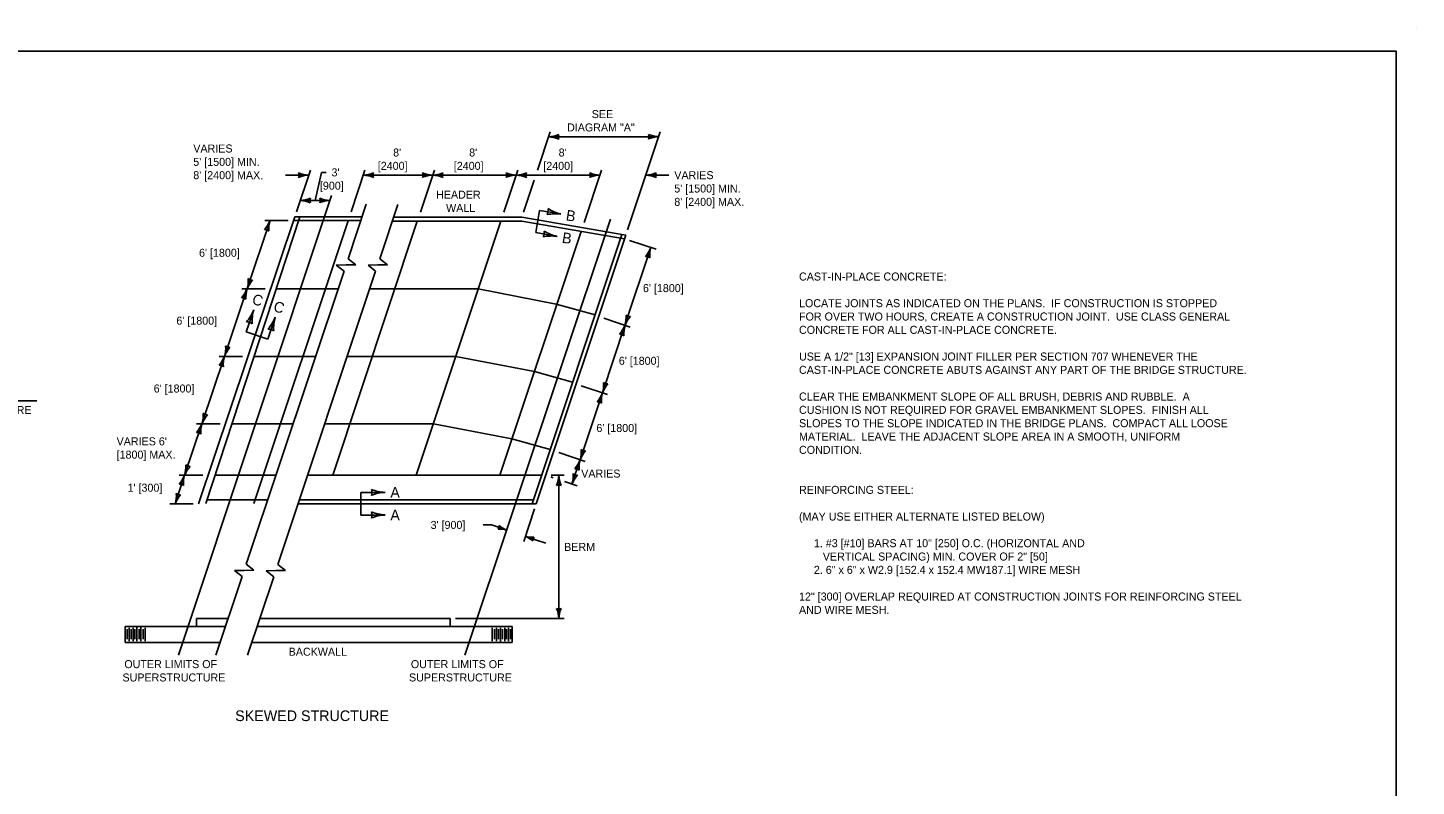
# Model space of a CAD drawing. Extents: x 49991.4 to 50021, y 49987.6 to 50011.4.
# Drawn here: x 50006.49 to 50016.9, y 49993.49 to 49999.18 of the extents above; entities that cross this region are included whole.
import ezdxf

# ---------------------------------------------------------------- set-up
doc = ezdxf.new("R2010")
doc.units = 0
for name, color, linetype in [('Level 1', 7, 'Continuous'), ('Level 2', 7, 'Continuous'), ('Level 3', 7, 'Continuous'), ('Level 4', 7, 'Continuous'), ('Level 5', 7, 'Continuous'), ('Level 6', 7, 'Continuous')]:
    doc.layers.add(name, color=color, linetype=linetype)

msp = doc.modelspace()

# ---------------------------------------------------------------- linework, layer by layer
at = {"layer": 'Level 1'}
for p, q in [((50016.9, 49999.176), (50016.9, 49999.176)), ((50008.492, 49997.757), (50007.772, 49995.606)), ((50007.825, 49995.608), (50008.53, 49997.757)), ((50008.997, 49997.757), (50008.492, 49997.757)), ((50009.234, 49997.754), (50010.194, 49997.754)), ((50010.194, 49997.754), (50010.975, 49997.621)), ((50008.186, 49995.607), (50008.893, 49997.728)), ((50008.482, 49997.729), (50008.987, 49997.729)), ((50008.777, 49995.82), (50009.411, 49997.724)), ((50009.224, 49997.724), (50010.194, 49997.724)), ((50009.403, 49995.82), (50010.038, 49997.724)), ((50010.03, 49995.82), (50010.639, 49997.648)), ((50010.194, 49997.724), (50010.965, 49997.593)), ((50010.272, 49995.606), (50010.945, 49997.626)), ((50010.303, 49995.606), (50010.975, 49997.621)), ((50008.817, 49997.217), (50008.353, 49997.217)), ((50009.055, 49997.217), (50009.867, 49997.217)), ((50009.867, 49997.217), (50010.453, 49997.103)), ((50010.453, 49997.103), (50010.744, 49997.022)), ((50008.648, 49996.711), (50008.187, 49996.711)), ((50008.886, 49996.711), (50009.7, 49996.711)), ((50009.7, 49996.711), (50010.289, 49996.597)), ((50010.289, 49996.597), (50010.575, 49996.517)), ((50008.48, 49996.206), (50008.022, 49996.206)), ((50009.532, 49996.206), (50008.718, 49996.206)), ((50009.532, 49996.206), (50010.121, 49996.092)), ((50010.121, 49996.092), (50010.407, 49996.012)), ((50008.351, 49995.82), (50007.895, 49995.82)), ((50008.589, 49995.82), (50010.343, 49995.82)), ((50008.518, 49995.606), (50010.303, 49995.606)), ((50007.755, 49994.685), (50007.755, 49994.744)), ((50007.755, 49994.744), (50007.993, 49994.744)), ((50008.23, 49994.744), (50009.657, 49994.744)), ((50009.657, 49994.685), (50009.657, 49994.744)), ((50007.22, 49994.566), (50007.22, 49994.685)), ((50007.22, 49994.685), (50007.755, 49994.685)), ((50007.235, 49994.59), (50007.235, 49994.664)), ((50007.25, 49994.574), (50007.25, 49994.676)), ((50007.265, 49994.59), (50007.265, 49994.665)), ((50007.28, 49994.574), (50007.28, 49994.676)), ((50007.294, 49994.591), (50007.294, 49994.665)), ((50007.309, 49994.574), (50007.309, 49994.677)), ((50007.325, 49994.591), (50007.325, 49994.665)), ((50007.339, 49994.575), (50007.339, 49994.677)), ((50007.355, 49994.665), (50007.355, 49994.591)), ((50007.37, 49994.676), (50007.37, 49994.575)), ((50007.755, 49994.685), (50007.933, 49994.685)), ((50007.933, 49994.685), (50007.973, 49994.685)), ((50008.21, 49994.685), (50010.123, 49994.685)), ((50009.973, 49994.676), (50009.973, 49994.574)), ((50009.991, 49994.664), (50009.991, 49994.59)), ((50010.006, 49994.574), (50010.006, 49994.676)), ((50010.021, 49994.59), (50010.021, 49994.664)), ((50010.036, 49994.573), (50010.036, 49994.676)), ((50010.051, 49994.59), (50010.051, 49994.664)), ((50010.067, 49994.574), (50010.067, 49994.676)), ((50010.081, 49994.59), (50010.081, 49994.665)), ((50010.096, 49994.574), (50010.096, 49994.676)), ((50010.111, 49994.591), (50010.111, 49994.665)), ((50010.123, 49994.685), (50010.123, 49994.566)), ((50007.22, 49994.566), (50007.933, 49994.566)), ((50008.171, 49994.566), (50010.123, 49994.566))]:
    msp.add_line(p, q, dxfattribs=at)
msp.add_lwpolyline([(49999.384, 49998.999), (50016.75, 49998.999), (50016.75, 49987.799), (49999.384, 49987.799)], close=True, dxfattribs=at)
at = {"layer": 'Level 3'}
for p, q in [((50010.312, 49998.108), (50010.408, 49998.396)), ((50010.988, 49997.659), (50011.233, 49998.396)), ((50010.395, 49998.358), (50011.221, 49998.358)), ((50008.423, 49998.07), (50008.597, 49998.07)), ((50008.61, 49998.108), (50008.505, 49997.795)), ((50008.692, 49998.091), (50008.645, 49997.88)), ((50008.692, 49998.091), (50008.728, 49998.091)), ((50008.916, 49997.795), (50009.019, 49998.108)), ((50009.007, 49998.07), (50009.518, 49998.07)), ((50009.434, 49997.792), (50009.54, 49998.108)), ((50009.518, 49998.07), (50010.147, 49998.07)), ((50010.061, 49997.792), (50010.166, 49998.108)), ((50010.147, 49998.07), (50010.78, 49998.07)), ((50010.661, 49997.715), (50010.793, 49998.108)), ((50011.125, 49998.07), (50011.298, 49998.07)), ((50010.207, 49997.792), (50010.287, 49998.032)), ((50008.533, 49997.88), (50008.756, 49997.88)), ((50008.307, 49997.729), (50008.137, 49997.221)), ((50008.267, 49997.729), (50008.443, 49997.729)), ((50011.201, 49997.515), (50011.003, 49997.58)), ((50010.968, 49996.944), (50011.163, 49997.527)), ((50008.137, 49997.221), (50007.966, 49996.711)), ((50008.271, 49997.217), (50008.095, 49997.217)), ((50010.799, 49996.438), (50010.968, 49996.944)), ((50011.006, 49996.931), (50010.809, 49996.997)), ((50007.966, 49996.711), (50007.796, 49996.204)), ((50008.102, 49996.711), (50007.926, 49996.711)), ((50010.632, 49995.935), (50010.799, 49996.438)), ((50010.837, 49996.425), (50010.64, 49996.491)), ((50007.796, 49996.204), (50007.667, 49995.82)), ((50007.933, 49996.206), (50007.757, 49996.206)), ((50010.67, 49995.923), (50010.473, 49995.989)), ((50010.571, 49995.754), (50010.632, 49995.935)), ((50007.667, 49995.82), (50007.596, 49995.606)), ((50007.803, 49995.82), (50007.627, 49995.82)), ((50010.431, 49995.801), (50010.412, 49995.807)), ((50010.415, 49995.82), (50010.512, 49995.82)), ((50010.472, 49994.744), (50010.472, 49995.82)), ((50010.609, 49995.741), (50010.514, 49995.773)), ((50007.732, 49995.606), (50007.556, 49995.606)), ((50010.209, 49995.323), (50010.291, 49995.568)), ((50009.968, 49995.447), (50009.906, 49995.447)), ((50010.081, 49995.409), (50009.968, 49995.447)), ((50010.374, 49995.31), (50010.221, 49995.361)), ((50009.697, 49994.744), (50010.512, 49994.744))]:
    msp.add_line(p, q, dxfattribs=at)
for centre, radius, start, end in [((50010.384, 49998.591), 0.233, 272.8273, 292.0772), ((50010.386, 49998.136), 0.222, 67.456, 87.6395), ((50010.524, 49998.358), 0.0548, 162.1388, 197.8612), ((50011.23, 49998.581), 0.222, 247.456, 267.6395), ((50011.092, 49998.358), 0.0548, 342.1388, 17.8612), ((50011.232, 49998.126), 0.233, 92.8273, 112.0772), ((50008.606, 49998.292), 0.222, 247.5675, 267.751), ((50008.469, 49998.07), 0.0548, 342.2503, 17.9727), ((50008.609, 49997.838), 0.233, 92.9388, 112.1887), ((50008.995, 49998.303), 0.233, 272.8273, 292.0772), ((50008.998, 49997.848), 0.222, 67.456, 87.6395), ((50009.135, 49998.07), 0.0548, 162.1388, 197.8612), ((50009.536, 49998.292), 0.222, 247.456, 267.6395), ((50009.399, 49998.07), 0.0548, 342.1388, 17.8612), ((50009.539, 49997.838), 0.233, 92.8273, 112.0772), ((50009.516, 49998.303), 0.233, 272.8273, 292.0772), ((50009.518, 49997.848), 0.222, 67.456, 87.6395), ((50009.655, 49998.07), 0.0548, 162.1388, 197.8612), ((50010.163, 49998.292), 0.222, 247.456, 267.6395), ((50010.025, 49998.07), 0.0548, 342.1388, 17.8612), ((50010.165, 49997.838), 0.233, 92.8273, 112.0772), ((50010.142, 49998.303), 0.233, 272.8273, 292.0772), ((50010.144, 49997.848), 0.222, 67.456, 87.6395), ((50010.282, 49998.07), 0.0548, 162.1388, 197.8612), ((50010.789, 49998.292), 0.222, 247.456, 267.6395), ((50010.652, 49998.07), 0.0548, 342.1388, 17.8612), ((50010.792, 49997.838), 0.233, 92.8273, 112.0772), ((50011.113, 49998.303), 0.233, 272.8273, 292.0772), ((50011.115, 49997.848), 0.222, 67.456, 87.6395), ((50011.253, 49998.07), 0.0548, 162.1388, 197.8612), ((50008.522, 49998.113), 0.233, 272.8273, 292.0772), ((50008.524, 49997.658), 0.222, 67.456, 87.6395), ((50008.662, 49997.88), 0.0548, 162.1388, 197.8612), ((50008.765, 49998.102), 0.222, 247.456, 267.6395), ((50008.628, 49997.88), 0.0548, 342.1388, 17.8612), ((50008.768, 49997.648), 0.233, 92.8273, 112.0772), ((50010.319, 49997.808), 0.073, 332.3215, 8.0439), ((50010.45, 49997.47), 0.311, 83.01, 102.2599), ((50010.55, 49998.069), 0.296, 237.6387, 257.8222), ((50008.099, 49997.808), 0.222, 318.9465, 339.13), ((50008.266, 49997.607), 0.0548, 53.6293, 89.3517), ((50008.531, 49997.666), 0.233, 164.3178, 183.5677), ((50010.29, 49997.641), 0.073, 332.0507, 7.773), ((50010.522, 49997.9), 0.296, 237.3678, 257.5514), ((50010.419, 49997.303), 0.311, 82.7391, 101.989), ((50010.955, 49997.606), 0.222, 319.0211, 339.2046), ((50011.122, 49997.406), 0.0548, 53.7039, 89.4262), ((50011.387, 49997.465), 0.233, 164.3924, 183.6422), ((50007.911, 49997.28), 0.233, 344.3178, 3.5677), ((50008.343, 49997.137), 0.222, 138.9465, 159.13), ((50008.176, 49997.338), 0.0548, 233.6293, 269.3517), ((50007.927, 49997.296), 0.222, 318.9609, 339.1444), ((50008.094, 49997.095), 0.0548, 53.6437, 89.366), ((50008.359, 49997.154), 0.233, 164.3322, 183.582), ((50007.908, 49997.165), 0.296, 318.8966, 339.0801), ((50008.484, 49996.975), 0.311, 164.2679, 183.5177), ((50008.13, 49996.897), 0.073, 53.5794, 89.3018), ((50008.069, 49997.111), 0.296, 318.8261, 339.0096), ((50008.645, 49996.921), 0.311, 164.1974, 183.4472), ((50010.76, 49997.023), 0.222, 319.0075, 339.191), ((50011.193, 49996.881), 0.233, 164.3788, 183.6286), ((50010.744, 49997.006), 0.233, 344.3924, 3.6422), ((50011.176, 49996.865), 0.222, 139.0211, 159.2046), ((50011.009, 49997.065), 0.0548, 233.7039, 269.4262), ((50008.291, 49996.843), 0.073, 53.5089, 89.2312), ((50010.928, 49996.822), 0.0548, 53.6903, 89.4126), ((50007.742, 49996.774), 0.233, 344.3322, 3.582), ((50008.174, 49996.632), 0.222, 138.9609, 159.1444), ((50008.007, 49996.833), 0.0548, 233.6437, 269.366), ((50007.758, 49996.791), 0.222, 318.9256, 339.1091), ((50007.925, 49996.59), 0.0548, 53.6084, 89.3308), ((50008.19, 49996.648), 0.233, 164.2969, 183.5468), ((50010.575, 49996.5), 0.233, 344.3788, 3.6286), ((50011.007, 49996.359), 0.222, 139.0075, 159.191), ((50010.84, 49996.559), 0.0548, 233.6903, 269.4126), ((50010.592, 49996.516), 0.222, 319.0382, 339.2217), ((50011.024, 49996.375), 0.233, 164.4095, 183.6593), ((50010.759, 49996.316), 0.0548, 53.721, 89.4434), ((50007.589, 49996.286), 0.222, 318.9089, 339.0924), ((50008.021, 49996.143), 0.233, 164.2802, 183.5301), ((50007.573, 49996.269), 0.233, 344.2969, 3.5468), ((50008.005, 49996.127), 0.222, 138.9256, 159.1091), ((50007.838, 49996.328), 0.0548, 233.6084, 269.3308), ((50007.756, 49996.085), 0.0548, 53.5917, 89.3141), ((50010.408, 49995.998), 0.233, 344.4095, 3.6593), ((50010.84, 49995.857), 0.222, 139.0382, 159.2217), ((50010.673, 49996.057), 0.0548, 233.721, 269.4434), ((50007.443, 49995.883), 0.233, 344.2802, 3.5301), ((50007.875, 49995.74), 0.222, 138.9089, 159.0924), ((50007.708, 49995.941), 0.0548, 233.5917, 269.3141), ((50010.424, 49996.015), 0.222, 318.9645, 339.148), ((50010.857, 49995.873), 0.233, 164.3358, 183.5857), ((50007.459, 49995.899), 0.222, 319.013, 339.1966), ((50007.891, 49995.757), 0.233, 164.3843, 183.6342), ((50010.25, 49995.829), 0.222, 337.456, 357.6395), ((50010.705, 49995.831), 0.233, 182.8273, 202.0772), ((50010.347, 49995.817), 0.233, 344.3358, 3.5857), ((50010.779, 49995.675), 0.222, 138.9645, 159.148), ((50010.612, 49995.875), 0.0548, 233.6473, 269.3697), ((50010.592, 49995.814), 0.0548, 53.6473, 89.3697), ((50007.372, 49995.669), 0.233, 344.3843, 3.6342), ((50007.804, 49995.527), 0.222, 139.013, 159.1966), ((50007.636, 49995.728), 0.0548, 233.6959, 269.4182), ((50007.627, 49995.698), 0.0548, 53.6959, 89.4182), ((50009.181, 49995.987), 0.296, 247.456, 267.6395), ((50008.998, 49995.691), 0.073, 342.1388, 17.8612), ((50009.185, 49995.381), 0.311, 92.8273, 112.0772), ((50010.472, 49995.691), 0.0548, 72.1388, 107.8612), ((50009.181, 49995.818), 0.296, 247.456, 267.6395), ((50008.998, 49995.521), 0.073, 342.1388, 17.8612), ((50009.185, 49995.211), 0.311, 92.8273, 112.0772), ((50009.98, 49995.443), 0.0456, 323.4504, 359.1728), ((50010.028, 49995.222), 0.194, 74.1389, 93.3887), ((50010.147, 49995.582), 0.185, 228.7676, 248.9511), ((50010.155, 49995.188), 0.185, 48.7676, 68.9511), ((50010.274, 49995.548), 0.194, 254.1389, 273.3887), ((50010.323, 49995.327), 0.0456, 143.4504, 179.1728), ((50010.472, 49994.872), 0.0548, 252.1388, 287.8612), ((50010.239, 49994.733), 0.233, 2.8273, 22.0772), ((50010.694, 49994.735), 0.222, 157.456, 177.6395)]:
    msp.add_arc(centre, radius, start, end, dxfattribs=at)
at = {"layer": 'Level 4'}
for p, q in [((50008.29, 49995.635), (50007.834, 49995.635)), ((50008.528, 49995.636), (50010.282, 49995.636))]:
    msp.add_line(p, q, dxfattribs=at)
at = {"layer": 'Level 5'}
for p, q in [((50007.62, 49994.471), (50008.769, 49997.918)), ((50009.768, 49994.471), (50010.859, 49997.741)), ((50006.56, 49996.378), (50005.492, 49996.378))]:
    msp.add_line(p, q, dxfattribs=at)
at = {"layer": 'Level 6'}
for p, q in [((50008.892, 49997.443), (50009.028, 49997.852)), ((50009.13, 49997.443), (50009.265, 49997.849)), ((50010.328, 49997.806), (50010.299, 49997.639)), ((50010.328, 49997.806), (50010.488, 49997.779)), ((50010.299, 49997.639), (50010.459, 49997.611)), ((50008.892, 49997.443), (50008.95, 49997.398)), ((50009.13, 49997.443), (50009.187, 49997.398)), ((50008.129, 49995.152), (50008.862, 49997.35)), ((50008.366, 49995.15), (50009.099, 49997.35)), ((50008.804, 49997.395), (50008.877, 49997.397)), ((50008.804, 49997.395), (50008.862, 49997.35)), ((50008.877, 49997.397), (50008.95, 49997.398)), ((50009.042, 49997.395), (50009.115, 49997.397)), ((50009.042, 49997.395), (50009.099, 49997.35)), ((50009.115, 49997.397), (50009.187, 49997.398)), ((50008.129, 49996.894), (50008.185, 49997.059)), ((50008.29, 49996.84), (50008.345, 49997.003)), ((50008.129, 49996.894), (50008.29, 49996.84)), ((50008.988, 49995.691), (50009.169, 49995.691)), ((50008.988, 49995.691), (50008.988, 49995.521)), ((50008.988, 49995.521), (50009.169, 49995.521)), ((50008.129, 49995.152), (50008.186, 49995.107)), ((50007.902, 49994.471), (50008.098, 49995.06)), ((50008.041, 49995.105), (50008.113, 49995.106)), ((50008.041, 49995.105), (50008.098, 49995.06)), ((50008.113, 49995.106), (50008.186, 49995.107)), ((50008.139, 49994.471), (50008.335, 49995.058)), ((50008.277, 49995.102), (50008.35, 49995.104)), ((50008.277, 49995.102), (50008.335, 49995.058)), ((50008.35, 49995.104), (50008.423, 49995.105)), ((50008.366, 49995.15), (50008.423, 49995.105))]:
    msp.add_line(p, q, dxfattribs=at)

# ---------------------------------------------------------------- texts
at = {"layer": 'Level 2'}
for s, height, p in [('SEE', 0.06, (50010.719, 49998.498)), ('DIAGRAM "A"', 0.06, (50010.534, 49998.398)), ('VARIES', 0.06, (50007.732, 49998.24)), ("5' [1500] MIN.", 0.06, (50007.732, 49998.14)), ('[2400]', 0.06, (50009.115, 49998.11)), ("8'", 0.06, (50009.23, 49998.21)), ('[2400]', 0.06, (50009.685, 49998.11)), ("8'", 0.06, (50009.8, 49998.21)), ('[2400]', 0.06, (50010.356, 49998.11)), ("8'", 0.06, (50010.471, 49998.21)), ("8' [2400] MAX.", 0.06, (50007.732, 49998.04)), ("3'", 0.06, (50008.768, 49998.061)), ('VARIES', 0.06, (50011.338, 49998.04)), ('[900]', 0.06, (50008.681, 49997.961)), ("5' [1500] MIN.", 0.06, (50011.338, 49997.94)), ('HEADER', 0.06, (50009.552, 49997.894)), ("8' [2400] MAX.", 0.06, (50011.338, 49997.84)), ('WALL', 0.06, (50009.627, 49997.794)), ("6' [1800]", 0.06, (50007.775, 49997.458)), ('CAST-IN-PLACE CONCRETE:', 0.06, (50012.273, 49997.28)), ("6' [1800]", 0.06, (50011.103, 49997.193)), ('LOCATE JOINTS AS INDICATED ON THE PLANS.  IF CONSTRUCTION IS STOPPED', 0.06, (50012.273, 49997.08)), ('FOR OVER TWO HOURS, CREATE A CONSTRUCTION JOINT.  USE CLASS GENERAL', 0.06, (50012.273, 49996.98)), ("6' [1800]", 0.06, (50007.605, 49996.949)), ('CONCRETE FOR ALL CAST-IN-PLACE CONCRETE.', 0.06, (50012.273, 49996.88)), ('USE A 1/2" [13] EXPANSION JOINT FILLER PER SECTION 707 WHENEVER THE ', 0.06, (50012.273, 49996.68)), ("6' [1800]", 0.06, (50010.922, 49996.648)), ('CAST-IN-PLACE CONCRETE ABUTS AGAINST ANY PART OF THE BRIDGE STRUCTURE.', 0.06, (50012.273, 49996.58)), ("6' [1800]", 0.06, (50007.435, 49996.44)), ('CLEAR THE EMBANKMENT SLOPE OF ALL BRUSH, DEBRIS AND RUBBLE.  A', 0.06, (50012.273, 49996.38)), ('SUPERSTRUCTURE', 0.06, (50005.748, 49996.279)), ('CUSHION IS NOT REQUIRED FOR GRAVEL EMBANKMENT SLOPES.  FINISH ALL', 0.06, (50012.273, 49996.28)), ("6' [1800]", 0.06, (50010.754, 49996.144)), ('SLOPES TO THE SLOPE INDICATED IN THE BRIDGE PLANS.  COMPACT ALL LOOSE ', 0.06, (50012.273, 49996.18)), ("VARIES 6'", 0.06, (50007.157, 49996.044)), ('MATERIAL.  LEAVE THE ADJACENT SLOPE AREA IN A SMOOTH, UNIFORM', 0.06, (50012.273, 49996.08)), ('[1800] MAX.', 0.06, (50007.157, 49995.944)), ('CONDITION.', 0.06, (50012.273, 49995.98)), ('VARIES', 0.06, (50010.64, 49995.802)), ("1' [300]", 0.06, (50007.239, 49995.696)), ('A', 0.08, (50009.209, 49995.651)), ('REINFORCING STEEL:', 0.06, (50012.273, 49995.68)), ('A', 0.08, (50009.209, 49995.481)), ('(MAY USE EITHER ALTERNATE LISTED BELOW)', 0.06, (50012.273, 49995.48)), ('BERM', 0.06, (50010.512, 49995.252)), ('     1. #3 [#10] BARS AT 10" [250] O.C. (HORIZONTAL AND', 0.06, (50012.273, 49995.28)), ('        VERTICAL SPACING) MIN. COVER OF 2" [50]', 0.06, (50012.273, 49995.18)), ('     2. 6" x 6" x W2.9 [152.4 x 152.4 MW187.1] WIRE MESH', 0.06, (50012.273, 49995.08)), ('12" [300] OVERLAP REQUIRED AT CONSTRUCTION JOINTS FOR REINFORCING STEEL', 0.06, (50012.273, 49994.88)), ('AND WIRE MESH.', 0.06, (50012.273, 49994.78)), ('BACKWALL', 0.06, (50008.447, 49994.466)), ('OUTER LIMITS OF', 0.06, (50007.215, 49994.373)), ('OUTER LIMITS OF', 0.06, (50009.363, 49994.373)), ('SUPERSTRUCTURE', 0.06, (50007.201, 49994.273)), ('SUPERSTRUCTURE', 0.06, (50009.349, 49994.273)), ('SKEWED STRUCTURE', 0.08, (50008.046, 49993.976))]:
    msp.add_text(s, height=height, dxfattribs=at).set_placement(p)
for s, height, rotation, p in [('B', 0.08, 350.9001, (50010.521, 49997.732)), ('B', 0.08, 350.9001, (50010.492, 49997.564)), ('C', 0.08, 342.3629, (50008.166, 49997.107)), ('C', 0.08, 342.3629, (50008.326, 49997.053)), ("3' [900]", 0.06, 0.0643, (50009.511, 49995.417))]:
    msp.add_text(s, height=height, rotation=rotation, dxfattribs=at).set_placement(p)

doc.saveas('drawing.dxf')
